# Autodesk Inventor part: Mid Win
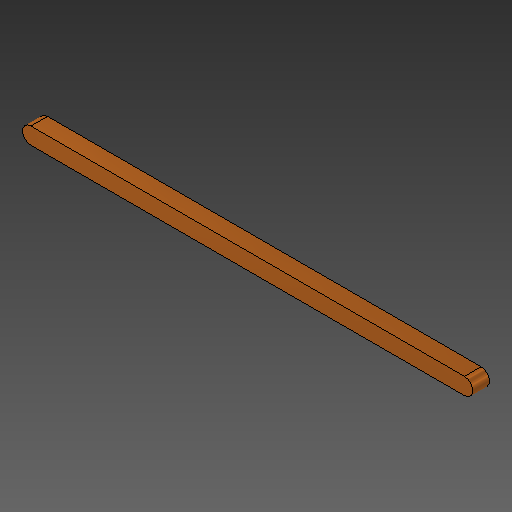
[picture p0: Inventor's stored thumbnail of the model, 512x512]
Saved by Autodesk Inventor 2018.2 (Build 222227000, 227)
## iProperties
Created: 2018-03
Part Number: Mid Win
Material: Gold
Document SubType Name: Modeling
Designer: PeterMaxwell-Stewart
Mass: 64.6198 g
Surface Area: 27.1781 cm^2
Volume: 3.34817 cm^3
Density: 19.3 g/cm^3
Appearance: Metal 1600F Hot
Author: PeterMaxwell-Stewart
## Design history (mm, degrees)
derived "O's and X's.ipt"
feature "Mid Win::O's and X's.ipt" dims "d0" = 10
tag "TaggingFeature1"
body "Solid1"
